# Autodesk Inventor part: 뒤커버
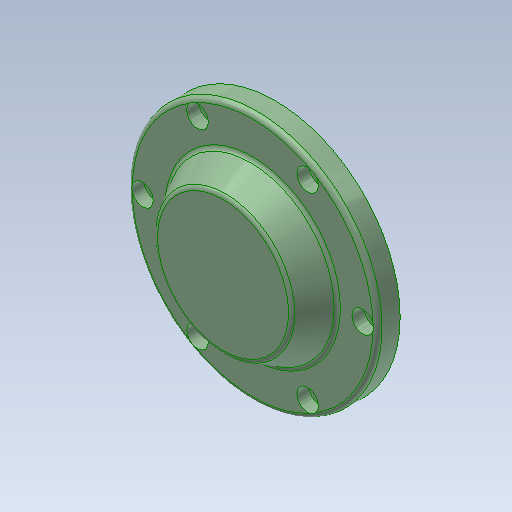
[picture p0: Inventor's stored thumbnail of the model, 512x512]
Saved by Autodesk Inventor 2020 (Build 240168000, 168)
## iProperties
Created: 2013-01
Part Number: 뒤커버
Document SubType Name: Modeling
Designer: 한국산업디자인학원[gmhk.co.kr]
Density: 2.71 g/cm^3
Material: 알루미늄 6061
Mass: 415.969 g
Surface Area: 272.105 cm^2
Volume: 153.494 cm^3
Appearance: 알루미늄 - 평지(1)
Author: 한국산업디자인학원[gmhk.co.kr]
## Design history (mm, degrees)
sketch "스케치2"
  geometry: L1 (-55, 0)-(55, 0) reference; L2 (35.98, -6)-(-35.98, -6) reference; L3 (-42.5, -25)-(-42.5, 0) reference; L4 (-37, -6)-(-37, 0); L5 (-55, 0)-(-55, 10); L6 (-55, 10)-(-37.5, 10); L7 (-37, -6)-(-42.5, -6); L8 (-37.5, 10)-(-29.994, 23); L9 (-29.994, 23)-(0, 23); L10 (-55, 0)-(-42.5, 0); L11 (-42.5, -6)-(-42.5, 0); L12 (0, 0)-(0, 23); L13 (0, 0)-(-37, 0)
  constraints: 22 end point, 4 perpendicular, 3 collinear, 2 parallel, 2 point on line, 1 vertical, 2 other
  dimensions: "d2" = 10 distance of L1.start L5.end; "d4" = 120 deg angle of L8 L6; "d5" = 13 distance between parallel lines of L6 L9; "d6" = 74 diameter of L4 L12; "d7" = 75 diameter of L6.end L12
revolve "회전1" sketch "스케치2" stored, may be unused: angle "d8" = 90 deg
fillet "모깎기1" dims "d9" = 2
sketch "스케치3"
  geometry: C1 r 2.067 at (48.5, 0) reference; 1 further point
hole "구멍1" sketch "스케치3" at (48.5, 0) diameter "d10" = 5.5; stored, may be unused: countersink angle "d14" = 90 deg, drill point angle "d16" = 118 deg; dims "d11" = 6, "d12" = 9.5, "d13" = 5.4, "d15" = 8
fillet "모깎기2" dims "d20" = 3
chamfer "모따기1" distance "d21" = 1; stored, may be unused: second distance "d22" = 2, angle "d23" = 45 deg
node "솔리드1"
pattern_circular "원형 패턴1" dims angle "d18" = 360 deg
node "참조1"
node "참조2"
node "참조3"
